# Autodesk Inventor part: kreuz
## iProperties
Shininess: 64.0
Length Units: 11269
Angle Units: 11279
Time Units: 11290
Mass Units: 11283
Length Display Precision: 3
Angle Display Precision: 2
Compacted: True
Part Number: kreuz
Document SubType Name: Modeling
Created: 2003-02
Material: Standard
Designer: Katja / W. Holzwarth
Density: 0.0
Volumn: 0.0
Area: 0.0
PropertySet Name: Model Information
Control State: 0
Master: False
Checked Out: False
Author: Katja / W. Holzwarth
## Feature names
1. Extrusion1
2. Extrusion2
3. Extrusion3
4. Extrusion4
5. Extrusion5
6. Runde Anordnung1 [Circular Pattern]
7. Rundung1 [Fillet]
8. Extrusion6
9. Extrusion7
10. Circular Pattern2
11. Fillet2
